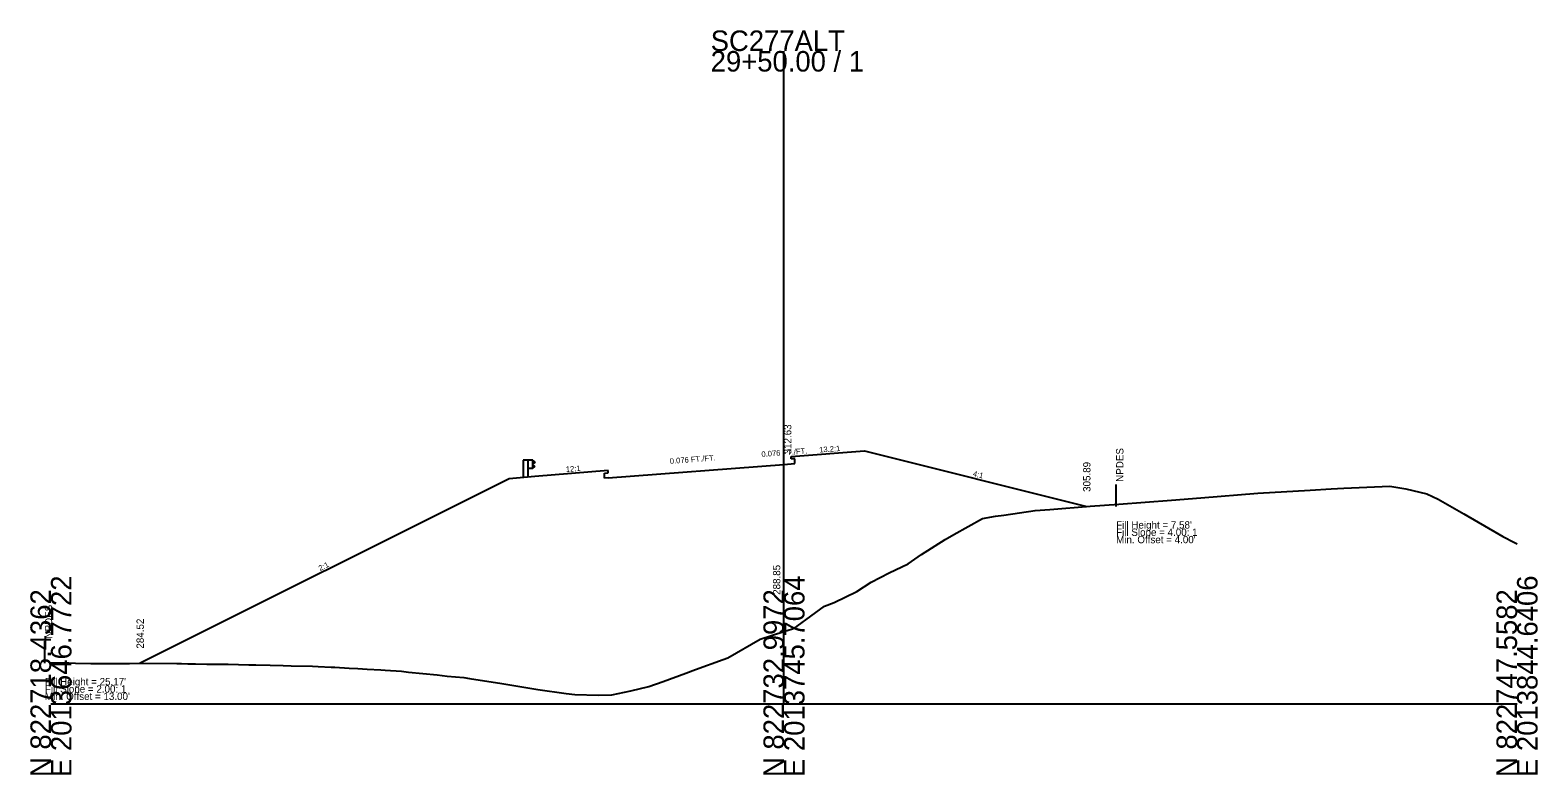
# Model space of a CAD drawing. Extents: x 205929 to 2357175, y -1785700 to 827636.
# Drawn here: x 2017417.3 to 2017623, y 827534.6 to 827636.1 of the extents above; entities that cross this region are included whole.
import ezdxf

# ---------------------------------------------------------------- set-up
doc = ezdxf.new("R2010")
doc.units = 0
for name, color, linetype in [('RD_GPK_XS_Cell', 7, 'Continuous'), ('RD_XS_Base', 7, 'Continuous'), ('RD_XS_EarthShd', 7, 'Continuous'), ('RD_XS_ExGround', 7, 'Continuous'), ('RD_XS_GR', 7, 'Continuous'), ('RD_XS_NPDES', 7, 'Continuous'), ('RD_XS_Pave', 7, 'Continuous'), ('RD_XS_TieSlope', 7, 'Continuous'), ('RD_XS_TX_Elev_EX', 7, 'Continuous'), ('RD_XS_TX_Elev_PR', 7, 'Continuous'), ('RD_XS_TX_ShdSlope', 7, 'Continuous'), ('RD_XS_TX_Slope', 7, 'Continuous'), ('RD_XS_TX_Warning', 7, 'Continuous')]:
    doc.layers.add(name, color=color, linetype=linetype)

msp = doc.modelspace()

# ---------------------------------------------------------------- linework, layer by layer
at = {"layer": 'RD_GPK_XS_Cell'}
for p, q in [((2017520.17, 827544.26), (2017520.17, 827633.25)), ((2017420.17, 827544.26), (2017520.17, 827544.26)), ((2017520.17, 827544.26), (2017620.17, 827544.26))]:
    msp.add_line(p, q, dxfattribs=at)
at = {"layer": 'RD_XS_Base'}
for p, q in [((2017496.17, 827575.07), (2017520.17, 827576.88)), ((2017520.17, 827576.88), (2017521.17, 827576.96))]:
    msp.add_line(p, q, dxfattribs=at)
at = {"layer": 'RD_XS_EarthShd'}
for p, q in [((2017521.17, 827577.96), (2017531.17, 827578.72)), ((2017496.17, 827576.07), (2017486.17, 827575.23)), ((2017486.17, 827575.23), (2017482.67, 827574.94))]:
    msp.add_line(p, q, dxfattribs=at)
at = {"layer": 'RD_XS_ExGround'}
msp.add_lwpolyline([(2017420.17, 827549.85), (2017421.81, 827549.83), (2017422.13, 827549.82), (2017422.62, 827549.82), (2017423.53, 827549.8), (2017425.62, 827549.76), (2017427.63, 827549.73), (2017428.23, 827549.74), (2017428.94, 827549.75), (2017429.43, 827549.75), (2017430.87, 827549.76), (2017432.2, 827549.77), (2017437.36, 827549.72), (2017437.99, 827549.72), (2017438.82, 827549.7), (2017439.91, 827549.69), (2017441.43, 827549.67), (2017443.99, 827549.64), (2017444.35, 827549.63), (2017447.16, 827549.57), (2017448.11, 827549.55), (2017450.06, 827549.51), (2017451.85, 827549.46), (2017452.94, 827549.43), (2017455.83, 827549.37), (2017456.6, 827549.35), (2017458.4, 827549.25), (2017458.9, 827549.22), (2017460.87, 827549.11), (2017462.05, 827549.04), (2017463.32, 827548.97), (2017465.18, 827548.86), (2017465.78, 827548.82), (2017467.98, 827548.68), (2017468.93, 827548.58), (2017472.87, 827548.18), (2017474.2, 827548.03), (2017476.48, 827547.84), (2017477.25, 827547.72), (2017481.66, 827547.01), (2017482.49, 827546.87), (2017486.06, 827546.28), (2017486.59, 827546.2), (2017490.47, 827545.65), (2017491.64, 827545.51), (2017494.87, 827545.41), (2017496.7, 827545.49), (2017499.28, 827546.01), (2017501.75, 827546.6), (2017503.68, 827547.31), (2017506.8, 827548.43), (2017508.09, 827548.93), (2017511.86, 827550.3), (2017512.5, 827550.5), (2017516.91, 827553.07), (2017520.17, 827554.1), (2017521.31, 827554.46), (2017521.97, 827554.85), (2017525.71, 827557.55), (2017527.02, 827558.07), (2017530.12, 827559.57), (2017532.07, 827560.85), (2017534.52, 827562.09), (2017537.13, 827563.33), (2017538.93, 827564.61), (2017542.18, 827566.64), (2017543.33, 827567.32), (2017547.23, 827569.52), (2017549.01, 827569.81), (2017550.18, 827569.98), (2017554.44, 827570.6), (2017556.44, 827570.75), (2017561.92, 827571.18), (2017565.86, 827571.48), (2017573.05, 827572.03), (2017577.03, 827572.33), (2017584.82, 827572.95), (2017591.97, 827573.37), (2017594.8, 827573.54), (2017596.56, 827573.64), (2017602.83, 827573.92), (2017605.01, 827573.57), (2017607.88, 827572.88), (2017609.42, 827572.13), (2017612.93, 827570.14), (2017617.67, 827567.39), (2017618.23, 827567.07), (2017619.84, 827566.24), (2017620.17, 827566.07)], dxfattribs=at)
at = {"layer": 'RD_XS_GR'}
for p, q in [((2017484.57, 827577.48), (2017484.57, 827575.1)), ((2017485.24, 827577.48), (2017484.57, 827577.48)), ((2017485.24, 827577.48), (2017485.24, 827575.15)), ((2017485.9, 827577.48), (2017485.24, 827577.48)), ((2017485.9, 827576.31), (2017485.24, 827576.31)), ((2017485.9, 827576.31), (2017485.9, 827577.48)), ((2017485.9, 827577.41), (2017486.17, 827577.21)), ((2017486.17, 827577.16), (2017485.9, 827576.96)), ((2017486.17, 827576.64), (2017485.9, 827576.84)), ((2017485.9, 827576.39), (2017486.17, 827576.59)), ((2017486.17, 827577.21), (2017486.17, 827577.16)), ((2017486.17, 827576.59), (2017486.17, 827576.64))]:
    msp.add_line(p, q, dxfattribs=at)
at = {"layer": 'RD_XS_NPDES'}
for p, q in [((2017565.48, 827571.14), (2017565.48, 827574.14)), ((2017419.34, 827549.77), (2017419.34, 827552.77))]:
    msp.add_line(p, q, dxfattribs=at)
at = {"layer": 'RD_XS_Pave'}
for p, q in [((2017521.17, 827577.63), (2017521.17, 827577.96)), ((2017496.17, 827575.74), (2017496.17, 827576.07)), ((2017521.67, 827577.67), (2017521.17, 827577.63)), ((2017521.17, 827576.96), (2017521.67, 827577)), ((2017521.67, 827577), (2017521.67, 827577.67)), ((2017495.67, 827575.7), (2017496.17, 827575.74)), ((2017495.67, 827575.03), (2017495.67, 827575.7)), ((2017496.17, 827575.07), (2017495.67, 827575.03))]:
    msp.add_line(p, q, dxfattribs=at)
at = {"layer": 'RD_XS_TieSlope'}
for p, q in [((2017531.17, 827578.72), (2017561.48, 827571.14)), ((2017482.67, 827574.94), (2017432.34, 827549.77))]:
    msp.add_line(p, q, dxfattribs=at)

# ---------------------------------------------------------------- texts
at = {"layer": 'RD_GPK_XS_Cell'}
for s, p in [('SC277ALT', (2017510.17, 827633.25)), ('29+50.00 / 1', (2017510.17, 827630.45))]:
    msp.add_text(s, height=2.8, dxfattribs=at).set_placement(p)
for s, p in [('E 2013646.7722', (2017422.97, 827534.26)), ('E 2013745.7064', (2017522.97, 827534.26)), ('E 2013844.6406', (2017622.97, 827534.26)), ('N 822718.4362', (2017420.17, 827534.26)), ('N 822732.9972', (2017520.17, 827534.26)), ('N 822747.5582', (2017620.17, 827534.26))]:
    msp.add_text(s, height=2.8, rotation=90, dxfattribs=at).set_placement(p)
at = {"layer": 'RD_XS_TX_Elev_EX'}
msp.add_text('288.85', height=1, rotation=90, dxfattribs=at).set_placement((2017519.67, 827559.1))
at = {"layer": 'RD_XS_TX_Elev_PR'}
for s, p in [(' 312.63', (2017521.17, 827577.88)), ('305.89', (2017561.98, 827573.14)), ('284.52', (2017432.84, 827551.77))]:
    msp.add_text(s, height=1, rotation=90, dxfattribs=at).set_placement(p)
at = {"layer": 'RD_XS_TX_ShdSlope'}
for s, rotation, p in [('13.2:1', 4.3347, (2017525, 827578.5)), ('12:1', 4.7636, (2017490.44, 827575.84))]:
    msp.add_text(s, height=0.75, rotation=rotation, dxfattribs=at).set_placement(p)
at = {"layer": 'RD_XS_TX_Slope'}
for s, rotation, p in [('0.076 FT./FT.', 4.3347, (2017504.62, 827576.96)), ('0.076 FT./FT.', 4.3347, (2017517.12, 827577.9)), ('4:1', 345.9638, (2017545.87, 827575.3)), ('2:1', 26.5651, (2017456.89, 827562.33))]:
    msp.add_text(s, height=0.75, rotation=rotation, dxfattribs=at).set_placement(p)
at = {"layer": 'RD_XS_TX_Warning'}
for p in [(2017566.48, 827574.14), (2017420.34, 827552.77)]:
    msp.add_text(' NPDES', height=1, rotation=90, dxfattribs=at).set_placement(p)
for s, p in [("Fill Height = 7.58' ", (2017565.48, 827568.14)), ('Fill Slope = 4.00: 1', (2017565.48, 827567.14)), ("Min. Offset = 4.00' ", (2017565.48, 827566.14)), ("Fill Height = 25.17' ", (2017419.34, 827546.77)), ('Fill Slope = 2.00: 1', (2017419.34, 827545.77)), ("Min. Offset = 13.00' ", (2017419.34, 827544.77))]:
    msp.add_text(s, height=1, dxfattribs=at).set_placement(p)

doc.saveas('drawing.dxf')
